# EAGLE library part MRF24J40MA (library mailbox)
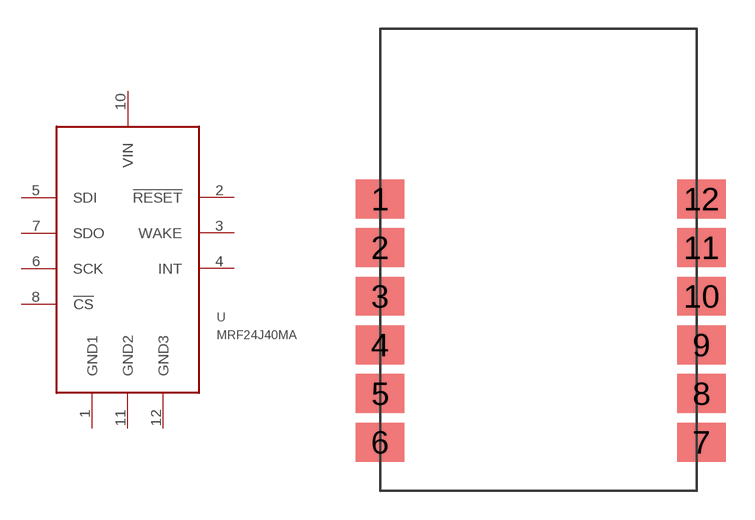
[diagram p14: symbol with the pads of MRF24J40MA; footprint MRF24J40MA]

Designator prefix -

## MRF24J40MA  [MRF24J40MA]
1  GND1
2  !RESET
3  WAKE
4  INT
5  SDI
6  SCK
7  SDO
8  !CS
10  VIN
11  GND2
12  GND3

## Footprint MRF24J40MA (pad centres in mm)
smd 2.54 x 2.032: 1 0,12.7; 2 0,10.16; 3 0,7.62; 4 0,5.08; 5 0,2.54; 6 0,0; 7 16.764,0; 8 16.764,2.54; 9 16.764,5.08; 10 16.764,7.62; 11 16.764,10.16; 12 16.764,12.7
